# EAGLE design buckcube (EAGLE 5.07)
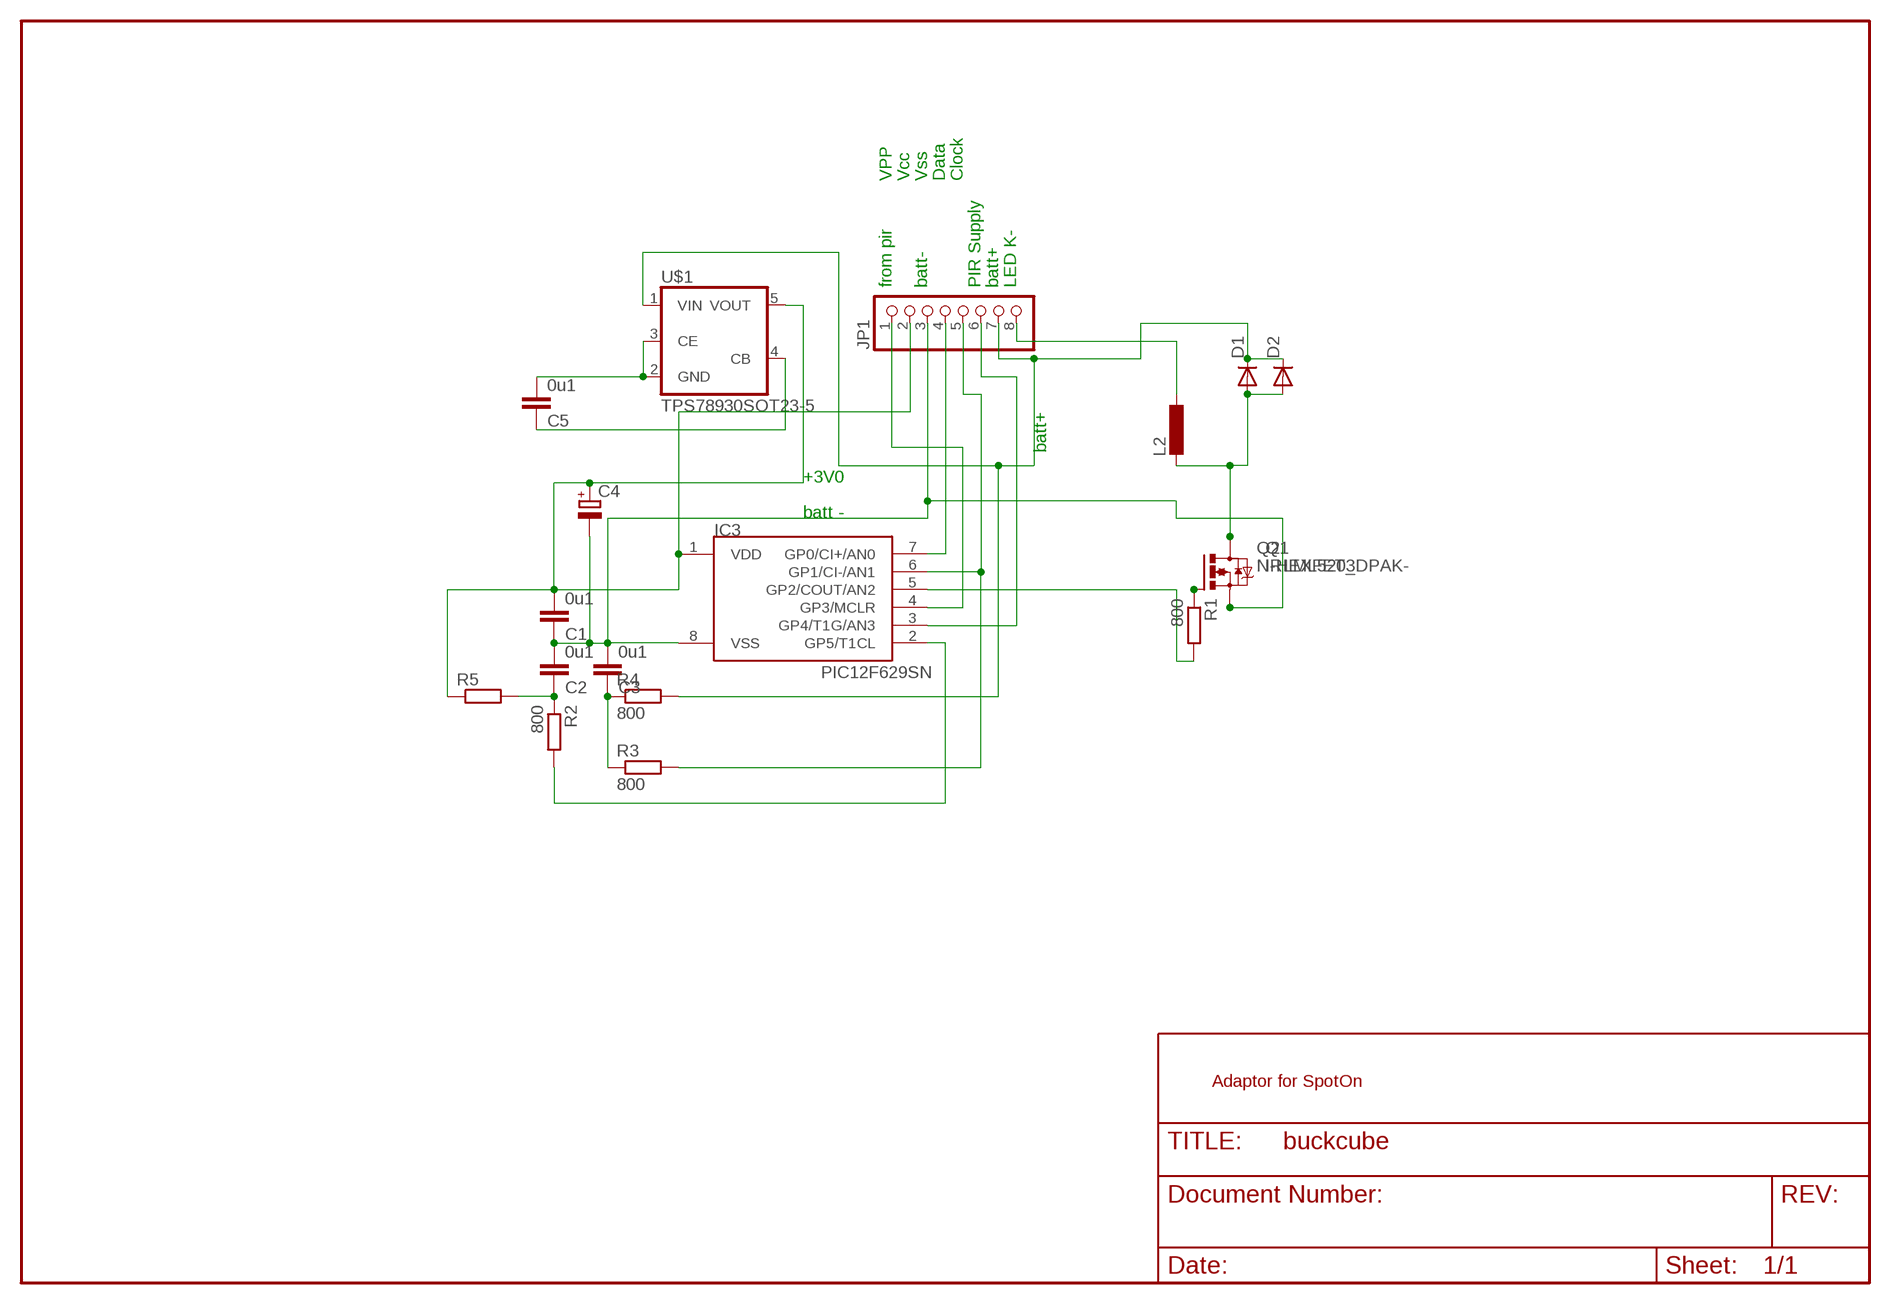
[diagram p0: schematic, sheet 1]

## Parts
C1  0u1  C-EUC1206  [C1206]
C2  0u1  C-EUC1206  [C1206]
C3  0u1  C-EUC1206  [C1206]
C4  CPOL-EUE2.5-6  [E2,5-6]
C5  0u1  C-EUC1206  [C1206]
D1  DIODE-SMC  [SMC]
D2  DIODE-SMB  [SMB]
IC3  PIC12F629SN  [SO-08]
JP1  PINHD-1X8  [1X08]
L2  L-EUOPEN  [OPEN5]
Q1  IRLML5203  [MICRO3]
Q2  N-HEXFET_DPAK-  [TO252]
R1  800  R-EU_R1206  [R1206]
R2  800  R-EU_R1206  [R1206]
R3  800  R-EU_R1206  [R1206]
R4  800  R-EU_R1206  [R1206]
R5  R-EU_0411/3V  [0411V]
U$1  TPS78930SOT23-5  [SOT25]

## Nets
N$1: C1.1 C2.2 C3.2 C4.- IC3.8(VSS) JP1.3 Q1.2(S) Q2.2(S)
N$2: IC3.2(GP5/T1CL) R2.2
N$3: D1.C D2.C JP1.7 R4.2 U$1.1(VIN)
N$4: IC3.6(GP1/CI-/AN1) JP1.5 R3.2
N$6: JP1.8 L2.1
N$7: C3.1 R3.1 R4.1
N$8: D1.A D2.A L2.2 Q1.3(D) Q2.3(D)
N$9: IC3.4(GP3/MCLR) JP1.1
N$11: C2.1 R2.1 R5.2
N$12: Q1.1(G) Q2.1(G) R1.1
N$13: C5.1 U$1.4(CB)
N$14: IC3.7(GP0/CI+/AN0) JP1.4
N$15: C5.2 U$1.2(GND) U$1.3(CE)
N$16: IC3.5(GP2/COUT/AN2) R1.2
N$17: IC3.3(GP4/T1G/AN3) JP1.6
V3: C1.2 C4.+ IC3.1(VDD) JP1.2 R5.1 U$1.5(VOUT)

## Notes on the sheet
- VPP | Vcc | Vss | Data | Clock
- from pir | batt- | PIR Supply | batt+ | LED K-
- batt+
- +3V0
- batt -
- Adaptor for SpotOn

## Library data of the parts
C1-C3 C5 = rcl:C-EU: CAPACITOR, European symbol
C4 = rcl(2):CPOL-EU: POLARIZED CAPACITOR, European symbol
D1 D2 = diode:DIODE-: DIODE
IC3 = microchip-3:PIC12F6*: uPC nW 1k Program Flash memory 2x Timer Comparator 10b A/D converter/ 4xIN
JP1 = pinhead(2):PINHD-1X8: PIN HEADER
L2 = rcl:L-EU: INDUCTOR, European symbol
Q1 = transistor-power:IRLML5203: HEXFET P-Channel Power MOSFET
Q2 = transistor-power:N-HEXFET_?-*: HEXFET® Power MOSFET
R1-R5 = rcl:R-EU_: RESISTOR, European symbol
U$1 = v-reg:TPS78930

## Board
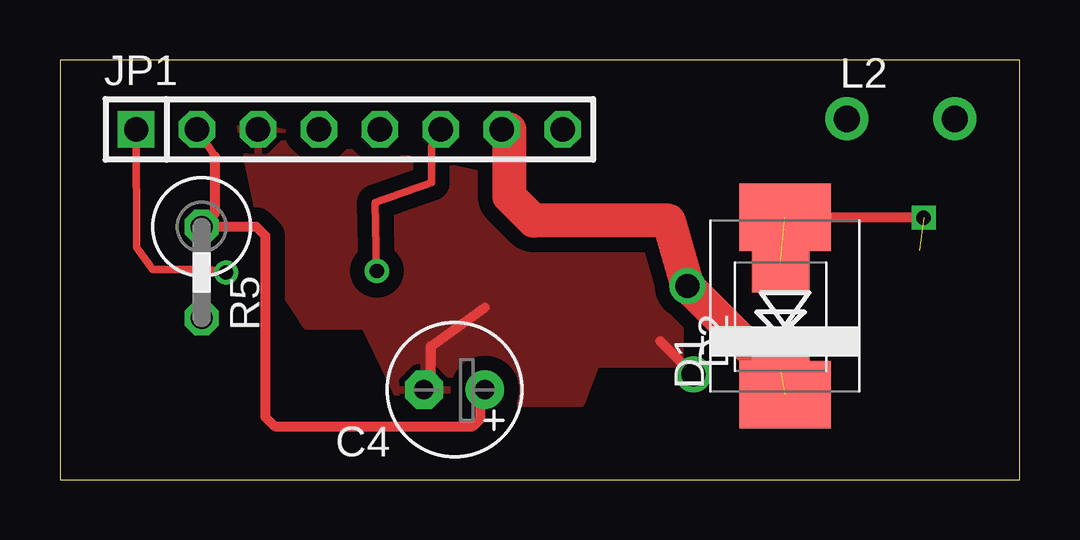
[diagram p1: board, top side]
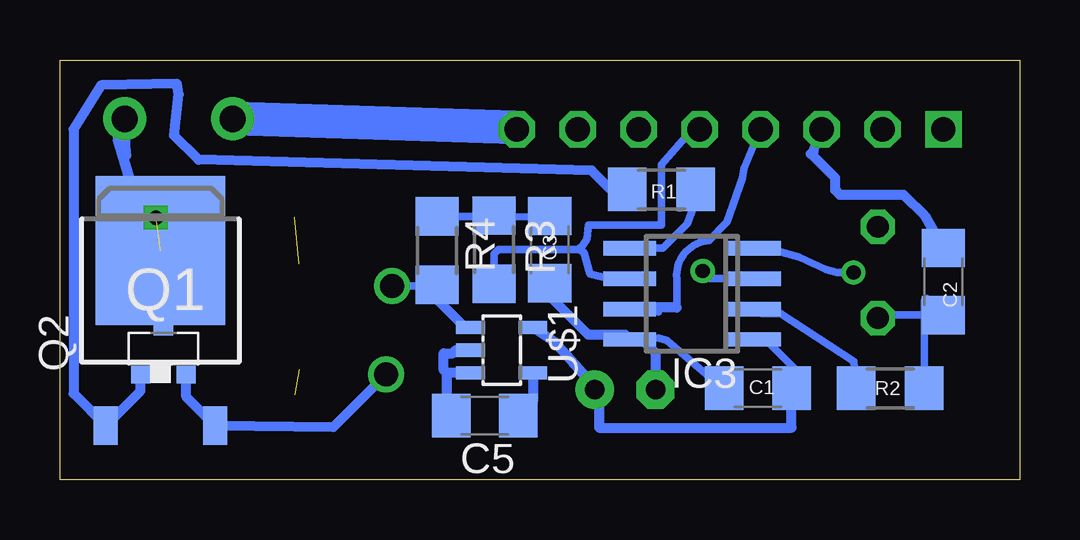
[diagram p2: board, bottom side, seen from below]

Size 40 x 17.5 mm. Coordinates in mm from the lower left corner, seen from the top.
Outline: 0,0 40,0 40,17.5 0,17.5 0,0
Copper layers (1*16): Top 0.035mm / dielectric 1.5mm / Bottom 0.035mm
Design rules "default": minimum track width 10mil, minimum drill 24mil, track to track 8mil, track to pad 8mil, pad to pad 8mil, via to via 8mil, smd to smd 8mil, copper to edge 1mil, drill to drill 8mil, minimum pad ring 10mil, minimum via ring 8mil, stop-mask expansion 4mil, vias tented up to drill 0mil, thermal gap 10mil

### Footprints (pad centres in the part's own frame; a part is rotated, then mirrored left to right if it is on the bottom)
C1206 = smd 1.6 x 1.8: 1 -1.4,0; 2 1.4,0
E2,5-6 = drill 0.813 pad 1.6 round: + -1.27,0 | drill 0.813 pad 1.6 octagon: - 1.27,0
SMC = smd 2.8 x 3.8: A 3.7,0; C -3.7,0
SMB = smd 2.4 x 2.4: A 2.2,0; C -2.2,0
SO-08 = smd 0.6 x 2.2: 1 -1.905,-2.6; 2 -0.635,-2.6; 3 0.635,-2.6; 4 1.905,-2.6; 5 1.905,2.6; 6 0.635,2.6; 7 -0.635,2.6; 8 -1.905,2.6
1X08 = drill 1.016 square: 1 -8.89,0 | drill 1.016 octagon: 2 -6.35,0; 3 -3.81,0; 4 -1.27,0; 5 1.27,0; 6 3.81,0; 7 6.35,0; 8 8.89,0
OPEN5 = drill 1.1 pad 1.778 round: 1 -2.25,0; 2 2.25,0
MICRO3 = smd 0.8 x 0.9: 1 -0.95,-1; 2 0.95,-1; 3 0,1
TO252 = smd 1 x 1.6: 1 -2.28,-3.53; 2 2.28,-3.53 | smd 5.4 x 6.2: 3 0,3.77
R1206 = smd 1.6 x 1.803: 1 -1.422,0; 2 1.422,0
0411V = drill 0.914 octagon: 1 -2.54,0; 2 1.27,0
SOT25 = smd 0.55 x 1.2: 1 -0.95,-1.3; 2 0,-1.3; 3 0.95,-1.3; 4 0.95,1.3; 5 -0.95,1.3

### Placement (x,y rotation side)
C1  10.91,3.81 0 bottom
C2  3.17,8.26 90 bottom
C3  19.58,9.59 270 bottom
C4  16.45,3.75 180 top
C5  22.29,2.67 180 bottom
D1  30.23,7.24 90 top
D2  30.04,6.79 90 top
IC3  13.65,7.75 90 bottom
JP1  12.06,14.61 0 top
L2  35.05,15.05 0 top
Q1  35.69,5.46 0 bottom
Q2  35.81,5.78 0 bottom
R1  14.93,12.1 0 bottom
R2  5.4,3.81 180 bottom
R3  21.91,9.59 270 bottom
R4  24.28,9.55 270 bottom
R5  5.91,8 270 top
U$1  21.59,5.4 270 bottom

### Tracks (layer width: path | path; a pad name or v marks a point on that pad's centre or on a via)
N$1  (via drill 1)
  Top 0.406: 17.71,7.18 15.46,5.56 15.46,4.03 C4.- | v26.42,4.38 25.02,5.78
  Bottom 0.305: IC3.8 15.77,5.87 15.05,5.91 14.7,5.81 12.33,3.76 C1.1
  Bottom 0.406: C2.2 3.94,10.99 4.83,11.87 7.49,11.87 7.68,12.06 7.68,12.57 8.7,13.59 8.59,13.7 JP1.3 | C4.- 15.18,5.28 15.77,5.87 | C3.2 19.58,7.65 17.97,6.03 16.44,6.03 IC3.8 | v26.42,4.38 28.61,2.19 Q2.2 34.74,3.45 Q1.2
  pour Top (isolate 0.61): 17.65,12.7 20.26,10.1 22.67,10.1 22.86,9.91 25.4,9.91 25.84,9.46 25.84,4.83 22.35,4.83 21.72,3.17 14.29,3.11 12.7,6.41 10.29,6.41 8.83,8.64 7.49,14.86
N$2
  Bottom 0.305: R2.2 6.9,4.94 9.97,6.92 10.73,6.92 10.99,7.18 IC3.2
N$3  (via drill 1)  (1 unrouted)
  Top 0.305: 26.15,8.12 26.35,8.89 26.35,8.57 v26.16,8.06
  Top 0.406: 29.57,4.66 D2.C
  Top 0.61: 18.73,14.61 JP1.7
  Top 1.422: 26.15,8.12 25.38,10.79 19.75,10.79 18.73,11.81 18.73,14.61 | v26.16,8.06 29.57,4.66
  Bottom 0.305: R4.2 24.48,8.06 v26.16,8.06
  Bottom 0.406: U$1.1 23.11,6.35 24.28,7.52 R4.2
N$4
  Bottom 0.305: IC3.6 17.14,8.38 17.91,8.57 18.16,9.46 18.41,9.59 | 18.41,9.59 18.35,9.59 18.35,9.65 18.29,9.65 18.03,10.03 17.97,10.6 14.92,10.6 14.92,13.14 14.06,14.14 JP1.5 | 18.41,9.59 21.72,9.59 21.91,9.4 R3.2
N$6
  Bottom 0.406: JP1.8 21.02,14.67
  Bottom 1.422: 21.02,14.67 L2.1
N$7
  Bottom 0.305: 21.93,11.01 21.97,11.05 | 21.93,11.01 R3.1 22,11.01 22.04,11.05 22.11,10.97 R4.1 | C3.1 21.85,10.93 21.93,11.01
N$8  (via drill 0.6)  (2 unrouted)
  Top 0.406: D1.A 35.99,10.94 v36.01,10.92
  Bottom 0.406: v36.01,10.92 36.89,11.87 37.59,14.22 37.24,13.53 L2.2 | Q2.3 35.81,6.59 Q1.3
N$9  (via drill 0.6)
  Top 0.305: JP1.1 3.2,9.69 3.87,8.76 6.22,8.76 v6.92,8.64
  Bottom 0.305: v6.92,8.64 7.62,8.64 8.06,8.76 9.21,9.27 10.1,9.53 10.92,9.53 IC3.4
N$11
  Bottom 0.305: 3.94,7.49 3.87,7.56 | 3.94,7.49 C2.1 5.21,6.86 5.78,6.99 R5.2 | R2.1 3.97,7.46 3.94,7.49
N$12
  Bottom 0.406: R1.1 17.05,12.1 17.84,12.89 34.23,13.34 35.24,14.35 35.05,16.07 35.12,16.51 38.29,16.45 39.43,14.61 39.43,3.59 Q2.1 36.64,3.71 Q1.1
N$13
  Bottom 0.406: U$1.4 20.29,3.27 C5.1
N$14
  Bottom 0.305: 15.05,6.99 15.62,7.04 IC3.7 | JP1.4 11.48,12.96 11.56,12.57 12.19,10.73 12.95,9.97 arc-90 14.29,8.38 14.29,7.18
  Bottom 0.406: 14.29,7.18 15.48,7.18 15.62,7.04
N$15
  Bottom 0.406: U$1.3 23.88,4.45 | 23.88,4.45 24,4.57 24,5.27 23.62,5.27 23.5,5.4 U$1.2 | 23.88,4.45 23.88,2.86 C5.2
N$16
  Bottom 0.305: R1.2 14.15,11.32 13.34,11.37 13.59,11.37 13.84,10.67 14.86,9.65 IC3.5
N$17  (via drill 0.6)
  Top 0.305: v13.21,8.7 13.14,11.56 15.49,12.38 15.49,13.91 16.11,14.52 | 16.11,14.52 16.19,14.61 | 16.11,14.52 JP1.6
  Bottom 0.305: IC3.3 12.89,8.38 v13.21,8.7
V3
  Top 0.305: 6.46,13.47 JP1.2
  Top 0.406: 6.46,13.47 6.46,11.1 R5.1 8.19,10.54 8.57,10.16 8.57,2.6 8.95,2.22 17.21,2.22 17.53,2.54 17.53,3.56 C4.+
  Bottom 0.305: 11.3,5.84 IC3.1 10.48,5.71 9,4.24 C1.2
  Bottom 0.406: U$1.5 19.43,5.78 17.65,3.81 C4.+ 17.53,3.75 17.53,2.16 9.51,2.16 C1.2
